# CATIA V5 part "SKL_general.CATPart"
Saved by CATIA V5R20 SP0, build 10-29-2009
Part number: SKL_general
Publications: "Plan_Ref", "G", "F", "A", "Plan_Sec", "Plan_Ter"
Bounding box of the stored display mesh (mm): x 0 to 0, y 0 to 24, z 0 to 5.85
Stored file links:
  C:\Users\MATT\Desktop\CATIA_Projet_IAO\CATIA FINAL\SKL_general.CATPart
  C:\Users\MATT\Desktop\CATIA_Projet_IAO\CATIA FINAL\SKL_Parametre_Projet_IAO.CATProduct
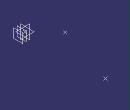
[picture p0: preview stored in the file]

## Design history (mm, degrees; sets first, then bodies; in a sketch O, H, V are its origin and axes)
External parameters (linked from other documents)
  External.AC = 3 mm
  External.Epaisseur = 1 mm
Set1
  Plane1 "Plan_Ref": type Offset, RefPlane yz-plane, Offset 0
  Point1 "G": (0, 0, 0)
  Point2 "F": (0, 24 {= 8*External.AC}, 0)
  Point3 "A": (0, 12 {= 4*External.AC}, 5.85 {= 1.95*External.AC})
  Plane2 "Plan_Sec": type Offset, RefPlane Plane1, Offset 1 {= External.Epaisseur}
  Plane3 "Plan_Ter": type Offset, RefPlane Plane2, Offset 1 {= External.Epaisseur}
Body1 (main body)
